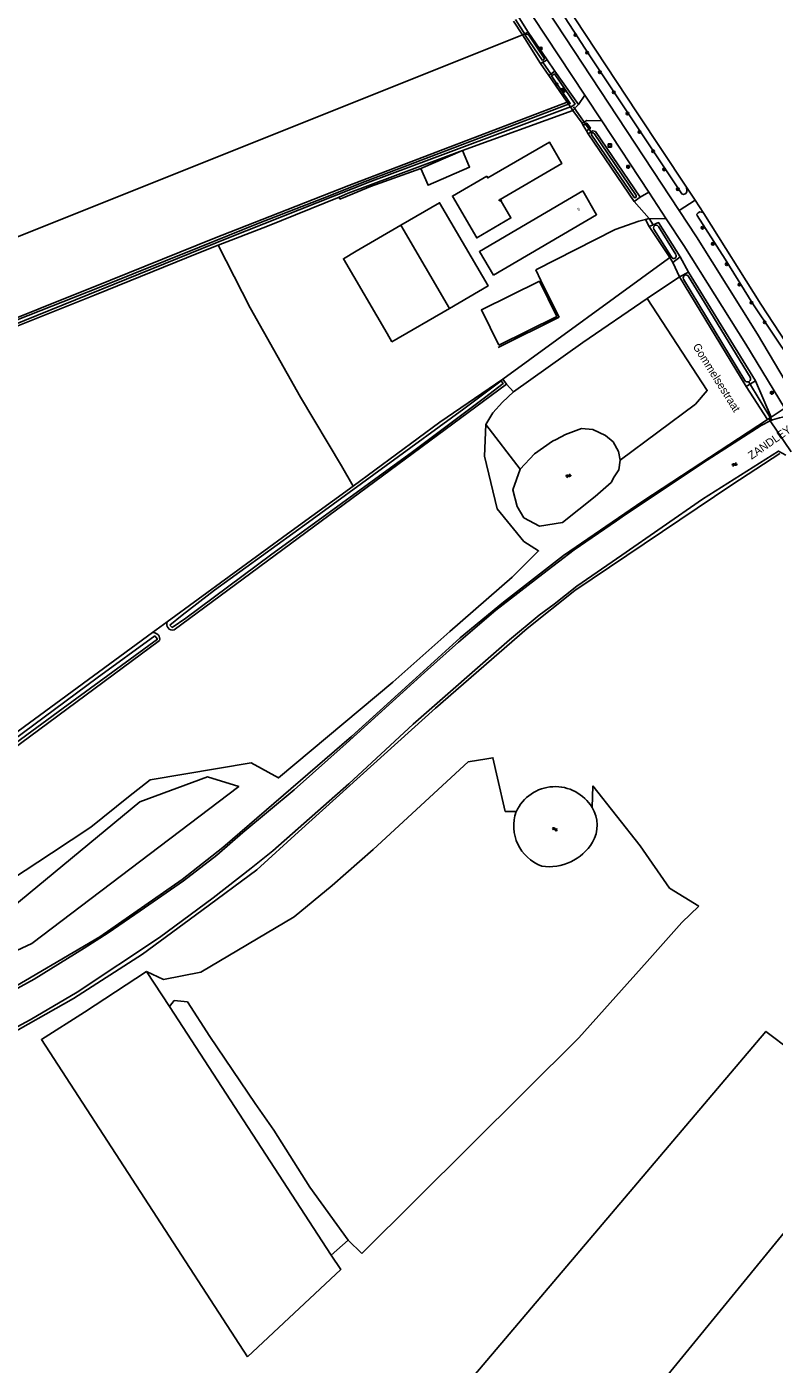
# Model space of a CAD drawing. Extents: x 137000 to 140001, y 403500 to 406000.
# Drawn here: x 138682 to 138915.5, y 404669.3 to 405087.1 of the extents above; entities that cross this region are included whole.
import ezdxf

# ---------------------------------------------------------------- set-up
doc = ezdxf.new("R2010")
doc.units = 0
for name, color, linetype in [('gg-afsc-draadraster', 7, 'Continuous'), ('gg-afsc-erfafscheiding', 7, 'Continuous'), ('gg-afsc-lijn draadraster', 7, 'Continuous'), ('gg-anno-huisnummerreeks BGT', 7, 'Continuous'), ('gg-anno-naam water', 7, 'Continuous'), ('gg-anno-openbare ruimte label', 7, 'Continuous'), ('gg-bbg-bijgebouw', 7, 'Continuous'), ('gg-bbg-hoofdgebouw', 7, 'Continuous'), ('gg-bbg-luifel en loopbrug', 7, 'Continuous'), ('gg-bbg-open loods', 7, 'Continuous'), ('gg-knt-bronhoudergrens', 7, 'Continuous'), ('gg-knt-onverhard', 7, 'Continuous'), ('gg-knt-verharding', 7, 'Continuous'), ('gg-knt-verharding nz', 7, 'Continuous'), ('gg-kntw-bovenkant insteek waterloop', 7, 'Continuous'), ('gg-kntw-greppel-droge sloot', 7, 'Continuous'), ('gg-kntw-waterlijn', 7, 'Continuous'), ('gg-kwrk-duiker nz buis', 7, 'Continuous'), ('gt-grn-groengrens', 7, 'Continuous'), ('gt-grn-groengrens NZ', 7, 'Continuous'), ('gt-grn-vlakafsluiter', 7, 'Continuous'), ('gt-grn-weggrens', 7, 'Continuous'), ('gt-symb-boom', 7, 'Continuous'), ('gt-symb-lichtmast', 7, 'Continuous'), ('gt-symb-lichtpunt', 7, 'Continuous'), ('gt-symb-rioolschacht', 7, 'Continuous'), ('gt-symb-watersymbool', 7, 'Continuous')]:
    doc.layers.add(name, color=color, linetype=linetype)

# ---------------------------------------------------------------- blocks, each defined once
blk = doc.blocks.new('gt0-BOOM')
at = {"layer": 'gt-symb-boom'}
for radius in [0.4, 0.2]:
    blk.add_circle((0, 0), radius, dxfattribs=at)
blk = doc.blocks.new('gt0-WA')
at = {"layer": 'gt-symb-watersymbool'}
for centre, start, end in [((-0.32, 0.02), 28.0725, 151.9275), ((0.43, 0.42), 208.0725, 331.9275), ((-0.32, -0.43), 28.0725, 151.9275), ((0.43, -0.03), 208.0725, 331.9275)]:
    blk.add_arc(centre, 0.425, start, end, dxfattribs=at)
blk = doc.blocks.new('gt0-RS')
at = {"layer": 'gt-symb-rioolschacht'}
blk.add_lwpolyline([(-0.5, -0.5), (0.5, -0.5), (0.5, 0.5), (-0.5, 0.5)], close=True, dxfattribs=at)
blk.add_circle((0, 0), 0.375, dxfattribs=at)
blk = doc.blocks.new('gt0-LMAST')
at = {"layer": 'gt-symb-lichtmast'}
for p, q in [((-0.18, 0.17), (-0.45, 0.44)), ((-0.01, 0.25), (-0.01, 0.62)), ((0.17, 0.17), (0.44, 0.44)), ((-0.26, 0), (-0.63, 0)), ((-0.18, -0.18), (-0.45, -0.45)), ((-0.01, -0.25), (-0.01, -0.63)), ((0.44, -0.45), (0.17, -0.18)), ((0.24, 0), (0.62, 0))]:
    blk.add_line(p, q, dxfattribs=at)
blk.add_circle((-0.01, 0), 0.25, dxfattribs=at)
blk = doc.blocks.new('gt0-LPUNT')
at = {"layer": 'gt-symb-lichtpunt'}
for p, q in [((0, 0), (-0.25, 0)), ((0, 0), (0.25, 0)), ((-0.18, -0.18), (-0.44, -0.44)), ((0, -0.25), (0, -0.62)), ((0.44, -0.44), (0.18, -0.18))]:
    blk.add_line(p, q, dxfattribs=at)
blk.add_arc((0, 0), 0.25, 180, 0, dxfattribs=at)

msp = doc.modelspace()

# ---------------------------------------------------------------- linework, layer by layer
at = {"layer": 'gg-afsc-draadraster'}
for points in [[(138892.01, 404812.38), (138882.8, 404818.07), (138873.68, 404831.21), (138858.86, 404849.96)], [(138719.46, 404792.04), (138700.08, 404779.33), (138686.6, 404770.76), (138751.02, 404671.65)]]:
    msp.add_lwpolyline(points, dxfattribs=at)
at = {"layer": 'gg-afsc-erfafscheiding'}
for p, q in [((138855.49, 405056.93), (138855.88, 405056.26)), ((138856.89, 405054.54), (138855.88, 405056.26)), ((138856.89, 405054.54), (138857.41, 405053.65)), ((138805.11, 405042.77), (138789.41, 405037.14)), ((138876.48, 405027.14), (138875.29, 405026.87)), ((138883.87, 405013.48), (138885.95, 405008.95))]:
    msp.add_line(p, q, dxfattribs=at)
at = {"layer": 'gg-afsc-lijn draadraster'}
for p, q in [((138865.81, 405023.71), (138873.19, 405026.4)), ((138873.19, 405026.4), (138875.29, 405026.87)), ((138841.01, 405011.17), (138865.81, 405023.71)), ((138842.61, 405007.82), (138841.01, 405011.17)), ((138848.3, 404996.36), (138842.61, 405007.82)), ((138829.33, 404986.93), (138848.3, 404996.36))]:
    msp.add_line(p, q, dxfattribs=at)
for points in [[(138892.01, 404812.38), (138882.8, 404818.07), (138873.68, 404831.21), (138858.86, 404849.96)], [(138719.46, 404792.04), (138700.08, 404779.33), (138686.6, 404770.76), (138751.02, 404671.65)]]:
    msp.add_lwpolyline(points, dxfattribs=at)
at = {"layer": 'gg-bbg-bijgebouw'}
for p, q in [((138784.98, 405016.96), (138798.91, 405025.09)), ((138814.07, 404999.1), (138798.91, 405025.09)), ((138814.07, 404999.1), (138796.12, 404988.65)), ((138794.62, 404991.22), (138796.12, 404988.65))]:
    msp.add_line(p, q, dxfattribs=at)
for points in [[(138825.71, 405040.41), (138814.98, 405034.16), (138822.58, 405021.12), (138833.29, 405027.36), (138829.92, 405033.15), (138849.2, 405044.38), (138845.3, 405051.06), (138826.03, 405039.85), (138825.71, 405040.41)], [(138794.62, 404991.22), (138780.97, 405014.62), (138784.98, 405016.96)]]:
    msp.add_lwpolyline(points, dxfattribs=at)
at = {"layer": 'gg-bbg-hoofdgebouw'}
msp.add_lwpolyline([(138827.79, 405009.46), (138860.04, 405028.36), (138855.69, 405035.78), (138823.44, 405016.87), (138827.79, 405009.46)], dxfattribs=at)
at = {"layer": 'gg-bbg-luifel en loopbrug'}
msp.add_line((138805.11, 405042.77), (138818.11, 405048.43), dxfattribs=at)
for points in [[(138805.11, 405042.77), (138807.38, 405037.55), (138820.38, 405043.22), (138818.11, 405048.43)], [(138814.07, 404999.1), (138826.13, 405006.13), (138810.97, 405032.12), (138798.91, 405025.09)]]:
    msp.add_lwpolyline(points, dxfattribs=at)
at = {"layer": 'gg-bbg-open loods'}
msp.add_lwpolyline([(138829.55, 404987.6), (138847.64, 404996.59), (138842.16, 405007.6), (138824.08, 404998.61), (138829.55, 404987.6)], dxfattribs=at)
at = {"layer": 'gg-knt-bronhoudergrens'}
for p, q in [((138836.9, 405084.5), (138447.33, 404928.72)), ((138789.41, 405037.14), (138780.9, 405033.64)), ((138888.1, 405036.95), (138890.79, 405032.91)), ((138779.59, 405033.82), (138779.84, 405033.2)), ((138780.9, 405033.64), (138779.84, 405033.2)), ((138890.79, 405032.91), (138893.55, 405028.77)), ((138875.82, 405002.18), (138885.95, 405008.95)), ((138831.86, 404975.47), (138834.08, 404973.06)), ((138825.48, 404962.82), (138836.14, 404948.88)), ((138725.95, 404901.23), (138721.35, 404897.86)), ((138858.86, 404849.96), (138858.62, 404843.24)), ((138726.61, 404781.07), (138719.46, 404792.04)), ((138782.39, 404708.09), (138786.7, 404703.88))]:
    msp.add_line(p, q, dxfattribs=at)
for points in [[(138741.88, 405018.82), (138751.85, 404999.32), (138767.58, 404971.37), (138780.35, 404949.98), (138784.02, 404943.59)], [(138830.76, 404976.96), (138882.45, 405014.66), (138882.89, 405014.98)], [(138875.82, 405002.18), (138855.72, 404988.44), (138834.08, 404973.06)], [(138867.37, 404951.71), (138890.89, 404969.24), (138894.6, 404973.48), (138875.82, 405002.18)], [(138825.48, 404962.82), (138827.6, 404966.48), (138830.61, 404969.83), (138834.08, 404973.06)], [(138541.15, 404756.75), (138615.86, 404809.1), (138630.26, 404799.78), (138645.29, 404802.53), (138664.34, 404815.45), (138677.25, 404820.74), (138689.74, 404828.99), (138702.01, 404837.04), (138713.87, 404846.56), (138720.64, 404851.85), (138752.18, 404857.14), (138760.64, 404852.49), (138796.42, 404882.33), (138814.2, 404898.21), (138833.67, 404915.14), (138838.75, 404920.22), (138841.92, 404923.38), (138837.27, 404926.31), (138828.96, 404936.47), (138825.04, 404952.94), (138825.48, 404962.82)], [(138825.7, 404858.44), (138819.93, 404857.5), (138790.21, 404830.12), (138777.4, 404818.82), (138765.52, 404809.11), (138736.42, 404791.79)], [(138829.11, 404852.35), (138827.63, 404858.75), (138825.7, 404858.44)], [(138554.59, 404758.55), (138551.38, 404755.43), (138554.96, 404748.26), (138560.28, 404744.96), (138567.45, 404743.58), (138575.89, 404746.24), (138607.39, 404763.42), (138665.15, 404792.25), (138683.61, 404800.7), (138748.26, 404849.74), (138738.53, 404852.76), (138717.39, 404844.97), (138674.71, 404809.67), (138607.7, 404775.82), (138591.16, 404769.68), (138554.59, 404758.55)], [(138829.11, 404852.35), (138831.49, 404842.01), (138834.92, 404841.93)], [(138875.79, 404795.11), (138886.65, 404807.27), (138892.01, 404812.38)], [(138786.7, 404703.88), (138854.51, 404771.27), (138875.79, 404795.11)], [(138719.46, 404792.04), (138724.76, 404789.52), (138736.42, 404791.79)], [(138795.51, 404634.93), (138912.95, 404773.27), (138928.9, 404761.22), (138931.58, 404758.11), (138945.79, 404743.66)], [(138945.79, 404743.66), (138886.04, 404670.61), (138813.08, 404581.5), (138816.79, 404594.38), (138818.73, 404606.25), (138822.87, 404620.33), (138817.65, 404621.14), (138815, 404623.92)], [(138751.02, 404671.65), (138780.13, 404698.9), (138777.17, 404703.43)]]:
    msp.add_lwpolyline(points, dxfattribs=at)
at = {"layer": 'gg-knt-onverhard'}
msp.add_lwpolyline([(138922.97, 404982.63), (138911.37, 405000.4), (138893.55, 405028.77)], dxfattribs=at)
at = {"layer": 'gg-knt-verharding'}
for p, q in [((138763.31, 405206.99), (138856.36, 405065.72)), ((138885.83, 405029.64), (138791.41, 405173.09)), ((138856.36, 405065.72), (138854.4, 405062.74)), ((138855.49, 405056.93), (138852.65, 405060.96)), ((138861.63, 405057.72), (138876.34, 405035.38)), ((138876.34, 405035.38), (138873.61, 405033.8)), ((138871.77, 405032.48), (138876.48, 405027.14)), ((138881.81, 405027.07), (138876.48, 405027.14))]:
    msp.add_line(p, q, dxfattribs=at)
for points in [[(138861.63, 405057.72), (138857, 405057.83), (138855.49, 405056.93)], [(138918.73, 404968.08), (138906.67, 404987.94), (138887.3, 405018.74), (138881.81, 405027.07)], [(138922.61, 404970.39), (138910.3, 404991.03), (138891.21, 405021.46), (138885.83, 405029.64)]]:
    msp.add_lwpolyline(points, dxfattribs=at)
at = {"layer": 'gg-knt-verharding nz'}
for p, q in [((138856.36, 405065.72), (138861.63, 405057.72)), ((138876.34, 405035.38), (138881.81, 405027.07))]:
    msp.add_line(p, q, dxfattribs=at)
at = {"layer": 'gg-kntw-bovenkant insteek waterloop'}
for p, q in [((138838.67, 405085.38), (138836.9, 405084.5)), ((138838.67, 405085.38), (138844.57, 405076.72)), ((138837.59, 405083.43), (138836.9, 405084.5)), ((138842.56, 405075.62), (138837.59, 405083.43)), ((138844.57, 405076.72), (138842.56, 405075.62)), ((138847.01, 405073.22), (138845.08, 405071.81)), ((138847.01, 405073.22), (138854.4, 405062.74)), ((138845.08, 405071.81), (138850.89, 405063.49)), ((138782.66, 405037.52), (138850.89, 405063.49)), ((138852.65, 405060.96), (138818.11, 405048.43)), ((138854.4, 405062.74), (138852.65, 405060.96)), ((138857.41, 405053.65), (138871.77, 405032.48)), ((138818.11, 405048.43), (138782.45, 405035.05)), ((138782.45, 405035.05), (138779.59, 405033.82)), ((138873.61, 405033.8), (138871.77, 405032.48)), ((138876.49, 405024.68), (138877.68, 405025.18)), ((138876.49, 405024.68), (138882.89, 405014.98)), ((138883.87, 405013.48), (138882.89, 405014.98)), ((138883.87, 405013.48), (138886.17, 405015.26)), ((138888.74, 405010.43), (138885.95, 405008.95)), ((138909.65, 404976.46), (138888.74, 405010.43)), ((138906.76, 404974.69), (138885.95, 405008.95)), ((138831.86, 404975.47), (138830.76, 404976.96)), ((138906.76, 404974.69), (138909.65, 404976.46)), ((138728.04, 404898.69), (138831.86, 404975.47)), ((138913.45, 404964.44), (138913.82, 404964.68)), ((138913.82, 404964.68), (138914.56, 404965.16)), ((138918.61, 404967.81), (138914.56, 404965.16)), ((138902.3, 404943.97), (138917.28, 404953.74)), ((138784.02, 404943.59), (138764.62, 404929.58)), ((138764.62, 404929.58), (138725.95, 404901.23)), ((138721.35, 404897.86), (138537.69, 404763.24)), ((138777.17, 404703.43), (138726.61, 404781.07)), ((138777.17, 404703.43), (138782.39, 404708.09))]:
    msp.add_line(p, q, dxfattribs=at)
for points in [[(138857.41, 405053.65), (138858.89, 405054.55), (138859.65, 405054.38), (138873.61, 405033.8)], [(138782.66, 405037.52), (138757.94, 405027.85), (138740.7, 405021.01), (138708.24, 405007.89), (138663.41, 404990.05), (138631.91, 404977.01), (138609.32, 404968.25), (138572.16, 404953.64), (138537.47, 404939.77), (138495.49, 404923.39), (138482.96, 404918.18), (138462.09, 404910.16), (138462.35, 404909.59)], [(138779.59, 405033.82), (138757.24, 405024.83), (138741.88, 405018.82)], [(138886.17, 405015.26), (138879.38, 405025.9), (138877.68, 405025.18)], [(138741.88, 405018.82), (138735.78, 405016.44), (138703.23, 405003.24), (138663, 404987.19), (138632.06, 404974.63), (138607.85, 404965.07), (138571.61, 404950.64), (138538.26, 404937.08), (138501.02, 404922.88), (138482.19, 404915.42), (138463.16, 404907.86)], [(138784.02, 404943.59), (138811.12, 404963.54), (138830.76, 404976.96)], [(138802.54, 404882.68), (138817.45, 404896.25), (138830.96, 404907.31), (138849.72, 404921.95), (138874.45, 404938.92), (138913.45, 404964.44)], [(138867.37, 404951.71), (138866.93, 404954.44), (138865.17, 404957.44), (138862.87, 404959.38), (138858.9, 404961.24), (138855.37, 404961.59), (138850.34, 404959.74), (138847.43, 404958.21)], [(138847.43, 404958.21), (138846.28, 404957.62), (138840.64, 404953.65), (138836.14, 404948.88)], [(138849.37, 404932.2), (138859.61, 404940.32), (138864.55, 404944.73), (138865.52, 404946.5), (138867.02, 404948.71), (138867.37, 404951.71)], [(138836.14, 404948.88), (138833.84, 404942.44), (138835.25, 404937.23), (138837.28, 404933.7), (138842.22, 404931.14), (138849.37, 404932.2)], [(138902.3, 404943.97), (138853.26, 404910.96), (138838.35, 404899.11), (138809.69, 404874.27), (138766.89, 404835.66), (138753.89, 404823.81), (138736.68, 404811.02), (138718.19, 404797.46), (138696.62, 404783.58), (138673.81, 404770.64), (138630.66, 404749.06), (138604.69, 404738.43), (138554.68, 404716.43), (138552.18, 404715.94), (138551.19, 404715.75)], [(138538.97, 404760.83), (138674.47, 404859.08), (138723.52, 404895.35)], [(138730.61, 404820.73), (138743.31, 404830.74), (138783.53, 404865.41), (138802.54, 404882.68)], [(138673.21, 404784.29), (138704.85, 404802.85), (138730.61, 404820.73)], [(138726.61, 404781.07), (138728.09, 404782.95), (138732.27, 404782.54)], [(138732.27, 404782.54), (138739.27, 404771.73), (138753.38, 404750.76), (138759.24, 404742.47), (138770.46, 404724.64), (138782.39, 404708.09)]]:
    msp.add_lwpolyline(points, dxfattribs=at)
for centre, radius, start, end in [((138727.59, 404900.45), 1.82, 154.402, 284.3849), ((138721.54, 404895.83), 2.04, 346.2934, 95.5788), ((138847.11, 404836.32), 13.42, 31.0107, 155.312), ((138849.64, 404837.7), 10.55, 329.8743, 31.6596), ((138847.54, 404837.47), 13.38, 160.5344, 249.6597), ((138845.24, 404840.49), 15.75, 261.3839, 329.1069)]:
    msp.add_arc(centre, radius, start, end, dxfattribs=at)
at = {"layer": 'gg-kntw-greppel-droge sloot'}
for points in [[(138798.99, 405172.67), (138798.39, 405173.13), (138797.53, 405173.06), (138797.04, 405172.43), (138797.14, 405171.47), (138798.47, 405169.36), (138826.12, 405126.35), (138841.38, 405103.56), (138857.7, 405078.33), (138886.65, 405034.9), (138887.18, 405034.7), (138887.9, 405034.97), (138888.23, 405035.5), (138888.23, 405035.76), (138888.1, 405036.95)], [(138798.99, 405172.67), (138815.07, 405148.73), (138833.99, 405119.01), (138872.71, 405060.2), (138888.1, 405036.95)], [(138922.97, 404982.63), (138922.9, 404982.23), (138922.61, 404981.73), (138922.21, 404981.4), (138921.75, 404981.53), (138921.12, 404982.16), (138908.89, 405000.49), (138900.18, 405014.48), (138891.5, 405028.17), (138891.37, 405028.57), (138891.76, 405028.96), (138892.26, 405029.26), (138893.18, 405029.07), (138893.55, 405028.77)]]:
    msp.add_lwpolyline(points, dxfattribs=at)
at = {"layer": 'gg-kntw-waterlijn'}
for p, q in [((138837.71, 405084.48), (138843.11, 405076.52)), ((138838.85, 405084.44), (138843.7, 405077.26)), ((138858.47, 405053.34), (138871.65, 405033.9)), ((138872.36, 405034.4), (138859.23, 405053.76)), ((138884.75, 405015.89), (138879.4, 405024.67)), ((138887.23, 405008.28), (138906.31, 404976.6))]:
    msp.add_line(p, q, dxfattribs=at)
for points in [[(138851.27, 405062.94), (138851.82, 405063.15), (138845.99, 405071.7), (138846.84, 405072.36), (138853.3, 405062.93), (138852.41, 405062.28), (138851.87, 405062.08)], [(138851.27, 405062.94), (138825.5, 405053.06), (138787.79, 405038.78), (138774.38, 405033.44), (138754.53, 405025.76), (138735.99, 405018.19), (138704.68, 405005.66), (138667.57, 404991.06), (138631.15, 404976.08), (138618.09, 404970.82), (138579.06, 404955.6), (138553.5, 404945.31), (138521.33, 404932.78), (138494.71, 404922.25), (138463.92, 404910.29), (138464.58, 404909.03), (138487.62, 404918.41), (138541.06, 404939.25), (138587.39, 404957.81), (138633.49, 404975.97), (138745.07, 405021.18), (138789.22, 405038.59), (138813.77, 405047.82), (138851.87, 405062.08)], [(138877.94, 405023.83), (138883.3, 405015.34), (138883.51, 405015.04)], [(138888.78, 405009.11), (138894.56, 404999.63), (138908, 404977.64)], [(138726.77, 404900.21), (138727.48, 404899.45), (138731.71, 404902.33), (138758.22, 404922.03), (138802.56, 404954.28), (138825.04, 404971.22), (138830.86, 404975.68), (138830.26, 404976.44), (138818.6, 404967.71), (138770.07, 404932.34), (138740.72, 404911.12), (138730.61, 404903.33), (138726.77, 404900.21)], [(138914.3, 404963.97), (138911.47, 404962.5), (138894.59, 404951.66), (138869.09, 404934.73)], [(138914.3, 404963.97), (138914.96, 404964.32), (138917.13, 404964.92), (138919.96, 404965.55)], [(138550.87, 404716.47), (138551.76, 404716.74), (138552.07, 404716.83), (138553.89, 404718.16), (138605.37, 404739.64), (138628.59, 404749.55), (138655.52, 404762.21), (138659.67, 404764.36), (138683.07, 404776.96), (138697.75, 404785.54), (138723.47, 404802.58), (138740.24, 404815), (138752.18, 404824.25), (138758.91, 404829.66), (138782.69, 404850.62), (138802.79, 404869.24), (138832.84, 404895.64), (138842.15, 404903.29), (138846.79, 404906.78), (138853.84, 404912.35), (138867.96, 404922.01), (138893.08, 404939.54), (138916.88, 404954.53), (138919.1, 404953.29)], [(138554.69, 404730.51), (138556.07, 404730.33), (138577.96, 404739.59), (138606.4, 404751.46), (138625.11, 404759.36), (138635.9, 404764.42), (138648.28, 404770.29), (138676.06, 404785.01), (138684.39, 404789.63), (138699.95, 404799.25), (138707.45, 404804.11), (138717.42, 404810.98), (138731, 404820.29), (138741.41, 404828.38), (138749.58, 404835.4), (138765.54, 404848.74), (138781.86, 404863.19), (138806.29, 404885.38), (138816.9, 404894.84), (138828.61, 404904.83), (138843.26, 404916.2), (138853.08, 404923.68), (138866.27, 404932.75), (138869.09, 404934.73)], [(138538.11, 404762.45), (138556.9, 404775.91), (138603.35, 404809.96), (138667.54, 404856.81), (138704.04, 404883.7), (138722.06, 404896.88)], [(138722.06, 404896.88), (138722.84, 404895.8), (138693.43, 404874.25), (138647.07, 404840.34), (138619.71, 404820.15), (138577.78, 404789.84), (138557.78, 404775.04), (138538.7, 404761.35)]]:
    msp.add_lwpolyline(points, dxfattribs=at)
for centre, radius, start, end in [((138838.26, 405083.99), 0.736, 37.1492, 138.523), ((138842.84, 405077.34), 0.87, 288.3589, 354.397), ((138858.85, 405053.55), 0.438, 28.7046, 208.7565), ((138872, 405034.15), 0.437, 214.9864, 35.0514), ((138878.67, 405024.25), 0.841, 29.7745, 209.8505), ((138884.13, 405015.46), 0.753, 214.6182, 34.6182), ((138888, 405008.69), 0.88, 27.9514, 207.9447), ((138907.15, 404977.12), 0.991, 211.52, 31.498)]:
    msp.add_arc(centre, radius, start, end, dxfattribs=at)
at = {"layer": 'gg-kwrk-duiker nz buis'}
for p, q in [((138834.67, 405089.37), (138837.87, 405084.45)), ((138843.09, 405076.08), (138845.94, 405072.07)), ((138858.29, 405054.1), (138852.85, 405062.02)), ((138914.8, 404964.25), (138907.45, 404976.3))]:
    msp.add_line(p, q, dxfattribs=at)
at = {"layer": 'gt-grn-groengrens'}
for p, q in [((138834.05, 405088.77), (138836.9, 405084.5)), ((138842.56, 405075.62), (138845.08, 405071.81)), ((138875.29, 405026.87), (138876.49, 405024.68)), ((138913.45, 404964.44), (138906.76, 404974.69))]:
    msp.add_line(p, q, dxfattribs=at)
at = {"layer": 'gt-grn-groengrens NZ'}
for p, q in [((138835.9, 405089.84), (138838.67, 405085.38)), ((138844.57, 405076.72), (138847.01, 405073.22)), ((138877.68, 405025.18), (138876.48, 405027.14)), ((138886.17, 405015.26), (138888.74, 405010.43)), ((138909.65, 404976.46), (138914.56, 404965.16))]:
    msp.add_line(p, q, dxfattribs=at)
at = {"layer": 'gt-grn-vlakafsluiter'}
for p, q in [((138850.89, 405063.49), (138851.27, 405062.94)), ((138851.27, 405062.94), (138851.87, 405062.08)), ((138851.87, 405062.08), (138852.65, 405060.96)), ((138913.82, 404964.68), (138914.3, 404963.97)), ((138920.85, 404954.27), (138914.3, 404963.97))]:
    msp.add_line(p, q, dxfattribs=at)
at = {"layer": 'gt-grn-weggrens'}
msp.add_line((138885.83, 405029.64), (138890.79, 405032.91), dxfattribs=at)
msp.add_lwpolyline([(138855.88, 405056.26), (138856.97, 405056.96), (138858.11, 405055.36), (138857.08, 405054.68), (138856.89, 405054.54)], dxfattribs=at)

# ---------------------------------------------------------------- block references
at = {"layer": 'gt-symb-boom'}
for p in [(138853.41, 405084.5), (138842.61, 405080.27), (138857.11, 405078.98), (138861.06, 405072.87), (138847.58, 405069.05), (138865.4, 405066.58), (138869.67, 405059.96), (138873.45, 405054.22), (138877.7, 405048.18), (138881.16, 405042.52), (138885.4, 405036.36), (138893.11, 405024.3), (138896.36, 405019.27), (138900.67, 405012.9), (138904.65, 405006.54), (138908.44, 405000.91), (138912.54, 404994.77)]:
    msp.add_blockref('gt0-BOOM', p, dxfattribs=at)
at = {"layer": 'gt-symb-lichtmast'}
for p in [(138869.87, 405043.37), (138914.79, 404972.77)]:
    msp.add_blockref('gt0-LMAST', p, dxfattribs=at)
at = {"layer": 'gt-symb-lichtpunt'}
msp.add_blockref('gt0-LPUNT', (138829.92, 405033.15), dxfattribs=at)
at = {"layer": 'gt-symb-rioolschacht'}
msp.add_blockref('gt0-RS', (138864.18, 405049.99), dxfattribs=at)
at = {"layer": 'gt-symb-watersymbool'}
for p, rotation in [((138849.67, 405067.16), 126.9958977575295), ((138851.2, 404946.79), 35.02487327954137), ((138903.08, 404950.32), 35.02487327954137), ((138847.05, 404836.43), 180)]:
    msp.add_blockref('gt0-WA', p, dxfattribs=dict(at, rotation=rotation))

# ---------------------------------------------------------------- texts
at = {"layer": 'gg-anno-huisnummerreeks BGT'}
msp.add_text('9', height=1, rotation=30.4, dxfattribs=at).set_placement((138854.33, 405029.42))
at = {"layer": 'gg-anno-naam water'}
msp.add_text('ZANDLEY', height=2.5, rotation=34.9451, dxfattribs=at).set_placement((138908.44, 404951.81))
at = {"layer": 'gg-anno-openbare ruimte label'}
msp.add_text('Gommelsestraat', height=2.5, rotation=302.1, dxfattribs=at).set_placement((138889.97, 404987.23))

doc.saveas('drawing.dxf')
